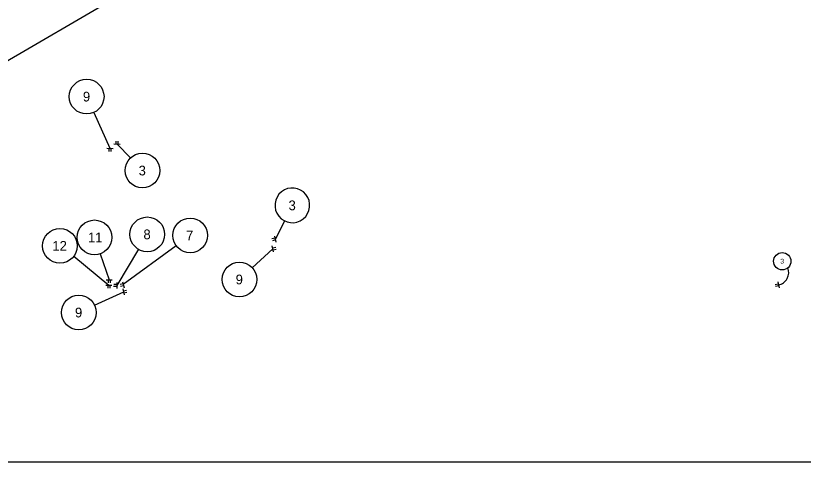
# Model space of a CAD drawing. Extents: x -87 to 2145, y -2128 to 440.
# Drawn here: x 272.2 to 677.4, y -1301.4 to -1071.8 of the extents above; entities that cross this region are included whole.
import ezdxf

# ---------------------------------------------------------------- set-up
doc = ezdxf.new("R2010")
doc.units = 0
for name, color, linetype in [('Default', 7, 'Continuous'), ('SC_Scratch1', 7, 'Continuous'), ('SN_P_Signs', 7, 'Continuous')]:
    doc.layers.add(name, color=color, linetype=linetype)

msp = doc.modelspace()

# ---------------------------------------------------------------- linework, layer by layer
at = {"layer": 'Default'}
for p, q in [((312.3, -1121.55), (320.57, -1139.97)), ((331.28, -1144.85), (324.35, -1137.83)), ((410.48, -1177.31), (405.78, -1186.72)), ((354.71, -1190.04), (327.47, -1210.06)), ((315.59, -1194.21), (320.23, -1207.61)), ((335.28, -1191.9), (324.22, -1210.56)), ((393.83, -1201.39), (404.48, -1191.64)), ((302.04, -1195.51), (320.14, -1210.32)), ((312.69, -1220.69), (327.7, -1213.78))]:
    msp.add_line(p, q, dxfattribs=at)
for centre, radius in [((308.64, -1113.41), 8.93), ((337.33, -1151.42), 8.93), ((312.68, -1185.77), 8.93), ((339.84, -1184.22), 8.93), ((361.91, -1184.75), 8.93), ((294.91, -1190.13), 8.93), ((666.53, -1198.04), 4.46), ((387.24, -1207.42), 8.93), ((304.57, -1224.42), 8.93)]:
    msp.add_circle(centre, radius, dxfattribs=at)
for centre, radius, start, end in [((414.47, -1169.32), 8.93, 308.9156, 308.3782), ((414.47, -1169.32), 8.93, 308.9156, 308.3782), ((663.27, -1203.79), 6.61, 282.2437, 20.8618)]:
    msp.add_arc(centre, radius, start, end, dxfattribs=at)
at = {"layer": 'SC_Scratch1'}
msp.add_line((902.07, -726.16), (-86.99, -1301.38), dxfattribs=at)
msp.add_lwpolyline([(-86.99, -726.16), (902.07, -726.16), (902.07, -1301.38), (-86.99, -1301.38)], close=True, dxfattribs=at)
at = {"layer": 'SN_P_Signs'}
for p, q in [((325.91, -1137.95), (322.71, -1137.83)), ((323.83, -1137.88), (323.89, -1136.28)), ((324.31, -1137.89), (324.31, -1137.89)), ((324.31, -1137.89), (324.31, -1137.89)), ((324.79, -1137.91), (324.85, -1136.31)), ((319.01, -1139.9), (322.2, -1140.02)), ((320.13, -1139.94), (320.06, -1141.54)), ((320.61, -1139.96), (320.61, -1139.96)), ((320.61, -1139.96), (320.61, -1139.96)), ((321.08, -1139.98), (321.02, -1141.58)), ((405.56, -1186.17), (404, -1186.54)), ((405.78, -1187.11), (404.22, -1187.47)), ((405.3, -1185.08), (406.04, -1188.2)), ((405.67, -1186.64), (405.67, -1186.64)), ((405.67, -1186.64), (405.67, -1186.64)), ((404.86, -1193.23), (404.13, -1190.11)), ((404.39, -1191.2), (405.95, -1190.84)), ((404.5, -1191.67), (404.5, -1191.67)), ((404.5, -1191.67), (404.5, -1191.67)), ((404.61, -1192.14), (406.17, -1191.77)), ((318.47, -1210.34), (321.67, -1210.33)), ((318.6, -1207.64), (321.8, -1207.63)), ((319.59, -1210.34), (319.59, -1211.94)), ((319.72, -1207.63), (319.72, -1209.23)), ((320.07, -1210.34), (320.07, -1210.34)), ((320.07, -1210.34), (320.07, -1210.34)), ((320.2, -1207.63), (320.2, -1207.63)), ((320.2, -1207.63), (320.2, -1207.63)), ((320.55, -1210.34), (320.55, -1211.94)), ((320.68, -1207.63), (320.68, -1209.23)), ((324.13, -1211.02), (322.53, -1210.98)), ((324.16, -1210.06), (322.56, -1210.02)), ((324.19, -1208.94), (324.1, -1212.14)), ((324.15, -1210.54), (324.15, -1210.54)), ((324.15, -1210.54), (324.15, -1210.54)), ((327.41, -1209.68), (325.86, -1210.05)), ((327.63, -1210.62), (326.08, -1210.98)), ((327.16, -1208.59), (327.89, -1211.71)), ((327.52, -1210.15), (327.52, -1210.15)), ((327.52, -1210.15), (327.52, -1210.15)), ((664.5, -1209.77), (662.94, -1210.13)), ((664.72, -1210.7), (663.16, -1211.06)), ((664.25, -1208.68), (664.97, -1211.79)), ((664.61, -1210.24), (664.61, -1210.24)), ((664.61, -1210.24), (664.61, -1210.24)), ((328.08, -1215.37), (327.35, -1212.25)), ((327.61, -1213.34), (329.16, -1212.98)), ((327.72, -1213.81), (327.72, -1213.81)), ((327.72, -1213.81), (327.72, -1213.81)), ((327.83, -1214.28), (329.38, -1213.91))]:
    msp.add_line(p, q, dxfattribs=at)

# ---------------------------------------------------------------- texts
at = {"layer": 'Default'}
for s, height, p in [('9', 5, (306.72, -1115.91)), ('3', 5, (335.38, -1153.92)), ('3', 5, (412.53, -1171.82)), ('8', 5, (337.87, -1186.72)), ('7', 5, (359.83, -1187.25)), ('11', 5, (309.32, -1188.27)), ('12', 5, (291.01, -1192.63)), ('3', 2.5, (665.56, -1199.29)), ('9', 5, (385.32, -1209.92)), ('9', 5, (302.65, -1226.92))]:
    msp.add_text(s, height=height, dxfattribs=at).set_placement(p)

doc.saveas('drawing.dxf')
